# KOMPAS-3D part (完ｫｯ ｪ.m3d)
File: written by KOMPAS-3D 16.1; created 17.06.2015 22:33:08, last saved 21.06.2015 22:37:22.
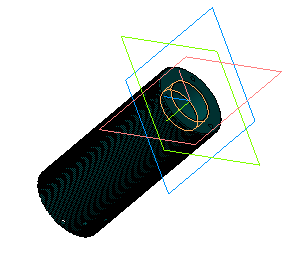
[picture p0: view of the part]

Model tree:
1. Эскиз:1
2. Операция выдавливания:1
     Расстояние 1 = 70
3. Фаска:1
     Угол = 45; Длина 1 = 0.5; Длина 2 = 0.5
4. Эскиз:2
5. Вырезать элемент выдавливания:1
     Расстояние 2 = 15; Расстояние 1 = 54
6. Эскиз:3
7. Вырезать элемент выдавливания:2
     Расстояние 2 = 15; Расстояние 1 = 63
8. Фаска:2
     Угол = 45; Длина 1 = 0.5; Длина 2 = 0.5
9. Эскиз:4
10. Вырезать элемент выдавливания:3
     Расстояние 2 = 75; Расстояние 1 = 63
11. Эскиз:5
12. Вырезать элемент выдавливания:4
     Расстояние 2 = 75; Расстояние 1 = 63
13. Массив по концентрической сетке:1  (with: Вырезать элемент выдавливания:4)  (15 pattern instances)
     Шаг 2 = 360; Шаг по оси = 5
14. Массив по концентрической сетке:2  (with: Вырезать элемент выдавливания:3)  (150 pattern instances)
     Шаг 2 = 360
15. Эскиз:6
16. Вырезать элемент выдавливания:5
     Расстояние 2 = 75; Расстояние 1 = 63
17. Массив по концентрической сетке:3  (with: Вырезать элемент выдавливания:5)  (3 pattern instances)
     Шаг 2 = 360
18. Условное изображение резьбы:1  (labels: Zebra 001; Сталь 20  ГОСТ 1050-88; SYSTEM_PROPERTY_ADDITIONAL_FOR:20.000000)
     Длина резьбы = 6; Шаг резьбы = 1; Номинальный диаметр резьбы = 18.0825

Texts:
  Body Specification ( left align )
  Body Specificaton ( centered )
